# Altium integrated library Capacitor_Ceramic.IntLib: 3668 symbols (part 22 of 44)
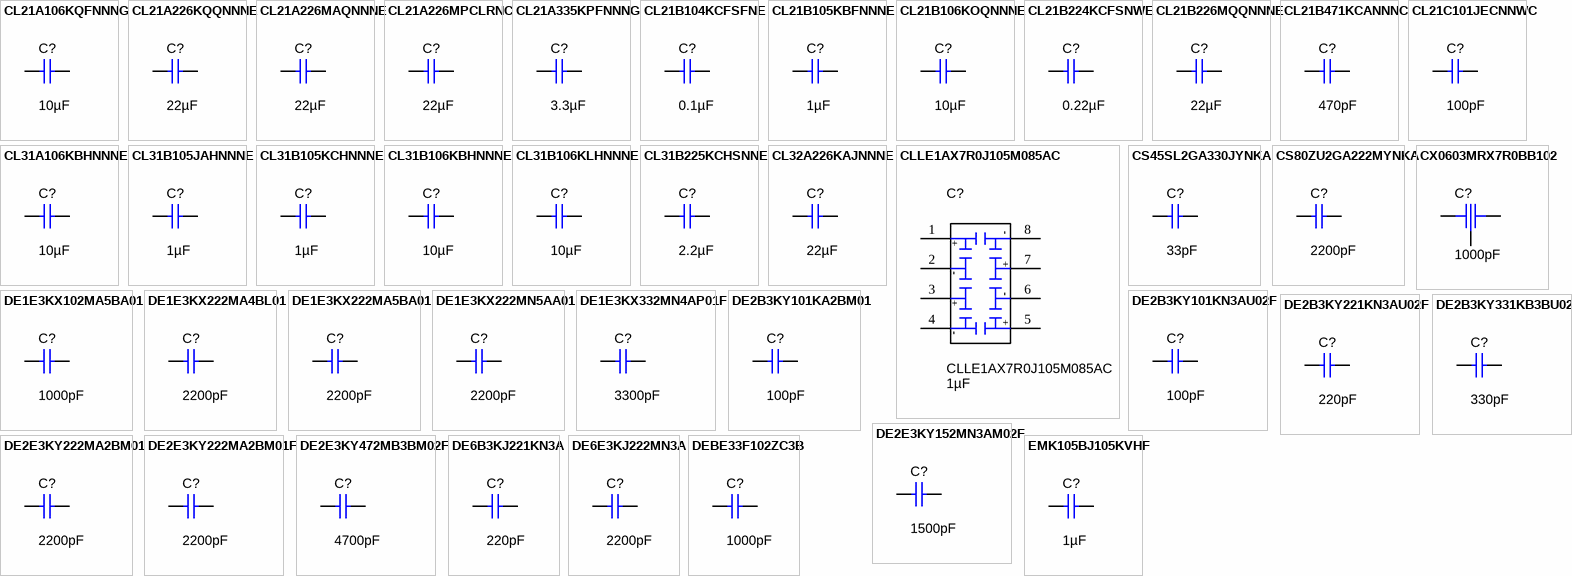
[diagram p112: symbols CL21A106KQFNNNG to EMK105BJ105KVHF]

## CL21C101JECNNWC
designator C?  ValueDisplayed: 100pF  (hidden comment: CL21C101JECNNWC)
CAP, CERM, 100 pF, 250 V,+/- 5%, C0G/NP0, 0805; Manufacturer: Samsung Electro-Mechanics; Polarized: N; CompType: Capacitor; Value: 100pF; U/M: EA; Cap_F: 0.0000000001; Tolerance_%: 5; VDC_V: 250; Value2: 250V; TaMin_C: -55; TaMax_C: 125; Cap_Case: 0805; SizeArea_mm2: 2.5; SizeAreaWB_mm2: 6.75; SizeX_mm: 2; SizeY_mm: 1.25; SizeZ_mm: 1.45; AEC Category: Q200
signal-integrity model Cap
simulation model Cap
footprint 0805_HV
footprint 0805_HV1
footprint 0805
footprint 0805M
footprint 0805L
pins: 1, 2

## CL31A106KBHNNNE
designator C?  ValueDisplayed: 10µF  (hidden comment: CL31A106KBHNNNE)
CAP, CERM, 10 µF, 50 V,+/- 10%, X5R, 1206; Manufacturer: Samsung Electro-Mechanics; Polarized: N; CompType: Capacitor; Value: 10uF; U/M: EA; Cap_F: 0.00001; Tolerance_%: 10; VDC_V: 50; Value2: 50V; TaMin_C: -55; TaMax_C: 85; Cap_Case: 1206; SizeArea_mm2: 5.12; SizeAreaWB_mm2: 10.92; SizeX_mm: 3.2; SizeY_mm: 1.6; SizeZ_mm: 1.9; AEC Category: Q200
signal-integrity model Cap
simulation model Cap
footprint 1206_190
footprint 1206_190M
footprint 1206_190L
pins: 1, 2

## CL31B105JAHNNNE
designator C?  ValueDisplayed: 1µF  (hidden comment: CL31B105JAHNNNE)
CAP, CERM, 1 µF, 25 V,+/- 5%, X7R, 1206; Manufacturer: Samsung Electro-Mechanics; Polarized: N; CompType: Capacitor; Value: 1uF; U/M: EA; Cap_F: 0.000001; Tolerance_%: 5; VDC_V: 25; Value2: 25V; TaMin_C: -55; TaMax_C: 125; Cap_Case: 1206; SizeArea_mm2: 5.12; SizeAreaWB_mm2: 10.92; SizeX_mm: 3.2; SizeY_mm: 1.6; SizeZ_mm: 1.9; AEC Category: Q200
signal-integrity model Cap
simulation model Cap
footprint 1206_190
footprint 1206_190M
footprint 1206_190L
pins: 1, 2

## CL31B105KCHNNNE
designator C?  ValueDisplayed: 1µF  (hidden comment: CL31B105KCHNNNE)
CAP, CERM, 1 µF, 100 V,+/- 10%, X7R, 1206; Manufacturer: Samsung Electro-Mechanics; Polarized: N; CompType: Capacitor; Value: 1uF; U/M: EA; Cap_F: 0.000001; Tolerance_%: 10; VDC_V: 100; Value2: 100V; TaMin_C: -55; TaMax_C: 125; Cap_Case: 1206; SizeArea_mm2: 5.12; SizeAreaWB_mm2: 10.92; SizeX_mm: 3.2; SizeY_mm: 1.6; SizeZ_mm: 1.8; AEC Category: Q200
signal-integrity model Cap
simulation model Cap
footprint 1206_180
footprint 1206_180M
footprint 1206_180L
pins: 1, 2

## CL31B106KBHNNNE
designator C?  ValueDisplayed: 10µF  (hidden comment: CL31B106KBHNNNE)
CAP, CERM, 10 µF, 50 V,+/- 10%, X7R, 1206; Manufacturer: Samsung Electro-Mechanics; Polarized: N; CompType: Capacitor; Value: 10uF; U/M: EA; Cap_F: 0.00001; Tolerance_%: 10; VDC_V: 50; Value2: 50V; TaMin_C: -55; TaMax_C: 125; Cap_Case: 1206; SizeArea_mm2: 5.12; SizeAreaWB_mm2: 10.92; SizeX_mm: 3.2; SizeY_mm: 1.6; SizeZ_mm: 1.8; AEC Category: Q200
signal-integrity model Cap
simulation model Cap
footprint 1206_180
footprint 1206_180M
footprint 1206_180L
pins: 1, 2

## CL31B106KLHNNNE
designator C?  ValueDisplayed: 10µF  (hidden comment: CL31B106KLHNNNE)
CAP, CERM, 10 µF, 35 V,+/- 10%, X7R, 1206; Manufacturer: Samsung Electro-Mechanics; Polarized: N; CompType: Capacitor; Value: 10uF; U/M: EA; Cap_F: 0.00001; Tolerance_%: 10; VDC_V: 35; Value2: 35V; TaMin_C: -55; TaMax_C: 125; Cap_Case: 1206; SizeArea_mm2: 5.12; SizeAreaWB_mm2: 10.92; SizeX_mm: 3.2; SizeY_mm: 1.6; SizeZ_mm: 1.9; AEC Category: Q200
signal-integrity model Cap
simulation model Cap
footprint 1206_190
footprint 1206_190M
footprint 1206_190L
pins: 1, 2

## CL31B225KCHSNNE
designator C?  ValueDisplayed: 2.2µF  (hidden comment: CL31B225KCHSNNE)
CAP, CERM, 2.2 µF, 100 V,+/- 10%, X7R, 1206; Manufacturer: Samsung Electro-Mechanics; Polarized: N; CompType: Capacitor; Value: 2.2uF; U/M: EA; Cap_F: 0.0000022; Tolerance_%: 10; VDC_V: 100; Value2: 100V; TaMin_C: -55; TaMax_C: 125; Cap_Case: 1206; SizeArea_mm2: 5.12; SizeAreaWB_mm2: 10.92; SizeX_mm: 3.2; SizeY_mm: 1.6; SizeZ_mm: 1.9; AEC Category: Q200; Green_Lifecycle: Active; Green_REACh: Passed
signal-integrity model Cap
simulation model Cap
footprint 1206_190
footprint 1206_190M
footprint 1206_190L
pins: 1, 2

## CL32A226KAJNNNE
designator C?  ValueDisplayed: 22µF  (hidden comment: CL32A226KAJNNNE)
CAP, CERM, 22 µF, 25 V,+/- 10%, X5R, 1210; Manufacturer: Samsung Electro-Mechanics; Polarized: N; CompType: Capacitor; Value: 22uF; U/M: EA; Cap_F: 0.000022; Tolerance_%: 10; VDC_V: 25; Value2: 25V; TaMin_C: -55; TaMax_C: 85; Cap_Case: 1210; SizeArea_mm2: 8; SizeAreaWB_mm2: 14.7; SizeX_mm: 3.2; SizeY_mm: 2.5; SizeZ_mm: 1.35; AEC Category: Q200
signal-integrity model Cap
simulation model Cap
footprint 1210
footprint 1210M
footprint 1210L
pins: 1, 2

## CLLE1AX7R0J105M085AC
designator C?  ValueDisplayed: 1µF
CAP, CERM, 1 µF, 6.3 V,+/- 20%, X7R, 0805; Manufacturer: TDK; SymbolCreator: a0411947; CompType: Capacitor; U/M: EA; Cap_F: 0.000001; Value: 1uF; Tolerance_%: 20; VDC_V: 6.3; Value2: 6.3V; TaMin_C: -55; TaMax_C: 125; Polarized: Y; Cap_Case: 0805; SizeArea_mm2: 2.5; SizeAreaWB_mm2: 6.75; SizeX_mm: 1.25; SizeY_mm: 2; SizeZ_mm: 0.95; AEC Category: Q200; AEC Qualified: N
footprint CLLE1A
pins: 1, 2, 3, 4, 5, 6, 7, 8

## CS45SL2GA330JYNKA
designator C?  ValueDisplayed: 33pF  (hidden comment: CS45SL2GA330JYNKA)
CAP, CERM, 33 pF, X1 440 VAC/Y2 300 VAC, +/- 5%, SL, D7xT5mm; Manufacturer: TDK; Polarized: N; CompType: Capacitor; Value: 33pF; U/M: EA; Cap_F: 0.000000000033; Tolerance_%: 5; TaMin_C: -25; TaMax_C: 125; Cap_Case: 7x5mm; SizeArea_mm2: 35; SizeAreaWB_mm2: 63; SizeX_mm: 7; SizeZ_mm: 11; AEC Category: Q200; AC_Safety: X1Y2; VAC_X: 440; VAC_Y: 300
signal-integrity model Cap
simulation model Cap
footprint TDK_700x500
pins: 1, 2

## CS80ZU2GA222MYNKA
designator C?  ValueDisplayed: 2200pF  (hidden comment: CS80ZU2GA222MYNKA)
CAP, CERM, 2200 pF, X1 440 VAC/Y2 300 VAC, +/- 20%, Z5U, D8xT5mm; Manufacturer: TDK; Polarized: N; CompType: Capacitor; Value: 2200pF; U/M: EA; Cap_F: 0.0000000022; Tolerance_%: 20; TaMin_C: 10; TaMax_C: 85; Cap_Case: 8x5x12mm; SizeArea_mm2: 40; SizeAreaWB_mm2: 70; SizeX_mm: 8; SizeY_mm: 5; SizeZ_mm: 12; AEC Category: Q200; AC_Safety: X1Y2; VAC_X: 440; VAC_Y: 300
signal-integrity model Cap
simulation model Cap
footprint CS_800x500x1200
pins: 1, 2

## CX0603MRX7R0BB102
designator C?  ValueDisplayed: 1000pF  (hidden comment: CX0603MRX7R0BB102)
CAP, CERM, 1000 pF, 100 V,+/- 20%, X7R, 0603; Manufacturer: Yageo America; SymbolCreator: a0411947; CompType: Capacitor; U/M: EA; Cap_F: 0.000000001; Value: 1000pF; Tolerance_%: 20; VDC_V: 100; Value2: 100V; TaMin_C: -55; TaMax_C: 125; Polarized: N; Cap_Case: 0603; SizeArea_mm2: 1.445514; SizeAreaWB_mm2: 4.960514; SizeX_mm: 1.626; SizeY_mm: 0.889; SizeZ_mm: 0.66; AEC Category: Q200
footprint X2Y_0603
pins: 1, 2, 3

## DE1E3KX102MA5BA01
designator C?  ValueDisplayed: 1000pF  (hidden comment: DE1E3KX102MA5BA01)
CAP, CERM, 1000 pF, X1 250 VAC/Y1 300 VAC, +/- 20%, E, Disc, 8x12mm; Manufacturer: MuRata; Polarized: N; CompType: Capacitor; Value: 1000pF; U/M: EA; Cap_F: 0.000000001; Tolerance_%: 20; TaMin_C: -25; TaMax_C: 85; Cap_Case: DE_800x1200x800; SizeArea_mm2: 64; SizeAreaWB_mm2: 100; SizeX_mm: 8; SizeZ_mm: 12; AEC Category: Q200; Green_Lifecycle: Not Set; Green_REACh: Incomplete; AC_Safety: X1Y1; VAC_X: 250; VAC_Y: 300
signal-integrity model Cap
simulation model Cap
footprint DE_800x1200x800
pins: 1, 2

## DE1E3KX222MA4BL01
designator C?  ValueDisplayed: 2200pF  (hidden comment: DE1E3KX222MA4BL01)
CAP, CERM, 2200 pF, X1 250 VAC/Y1 300 VAC, +/- 20%, E, Cap, 7x12x9 mm; Manufacturer: MuRata; Polarized: N; CompType: Capacitor; Value: 2200pF; U/M: EA; Cap_F: 0.0000000022; Tolerance_%: 20; TaMin_C: -25; TaMax_C: 85; Cap_Case: CAPRD1000W60D900H1200; SizeArea_mm2: 80.5; SizeAreaWB_mm2: 121.5; SizeX_mm: 11.5; SizeY_mm: 7; SizeZ_mm: 12.5; AEC Category: Q200; Green_Lifecycle: Not Set; Green_REACh: Incomplete; AC_Safety: X1Y1; VAC_X: 250; VAC_Y: 300
signal-integrity model Cap
simulation model Cap
footprint CAPRD1000W60D900H1200
pins: 1, 2

## DE1E3KX222MA5BA01
designator C?  ValueDisplayed: 2200pF  (hidden comment: DE1E3KX222MA5BA01)
CAP, CERM, 2200 pF, X1 250 VAC/Y1 300 VAC, +/- 20%, E, Disc 10x8mm; Manufacturer: MuRata; Polarized: N; CompType: Capacitor; Value: 2200pF; U/M: EA; Cap_F: 0.0000000022; Tolerance_%: 20; TaMin_C: -25; TaMax_C: 85; Cap_Case: CAPRD1000W60D1000H1400; SizeArea_mm2: 80; SizeAreaWB_mm2: 120; SizeX_mm: 10; SizeY_mm: 8; SizeZ_mm: 14; AEC Category: Q200; Green_Lifecycle: Not Set; Green_REACh: Incomplete; AC_Safety: X1Y1; VAC_X: 250; VAC_Y: 300
signal-integrity model Cap
simulation model Cap
footprint CAPRD1000W60D1000H1400
pins: 1, 2

## DE1E3KX222MN5AA01
designator C?  ValueDisplayed: 2200pF  (hidden comment: DE1E3KX222MN5AA01)
CAP, CERM, 2200 pF, X1 250 VAC/Y1 300 VAC, +/- 20%, E, 10.0x8.0x14.0mm; Manufacturer: MuRata; Polarized: N; CompType: Capacitor; Value: 2200pF; U/M: EA; Cap_F: 0.0000000022; Tolerance_%: 20; TaMin_C: -25; TaMax_C: 85; Cap_Case: 10x8x14mm; SizeArea_mm2: 80; SizeAreaWB_mm2: 120; SizeX_mm: 10; SizeY_mm: 8; SizeZ_mm: 14; AEC Category: Q200; AC_Safety: X1Y1; VAC_X: 250; VAC_Y: 300
signal-integrity model Cap
simulation model Cap
footprint KX_1000x800x1400
pins: 1, 2

## DE1E3KX332MN4AP01F
designator C?  ValueDisplayed: 3300pF  (hidden comment: DE1E3KX332MN4AP01F)
CAP, CERM, 3300 pF, X1 250 VAC/Y1 300 VAC, +/- 20%, E, D10xT7mm; Manufacturer: MuRata; Polarized: N; CompType: Capacitor; Value: 3300pF; U/M: EA; Cap_F: 0.0000000033; Tolerance_%: 20; TaMin_C: -40; TaMax_C: 125; Cap_Case: 10x7mm; SizeArea_mm2: 70; SizeAreaWB_mm2: 108; SizeX_mm: 10; SizeY_mm: 7; SizeZ_mm: 13; AEC Category: Q200; AC_Safety: X1Y1; VAC_X: 250; VAC_Y: 300
signal-integrity model Cap
simulation model Cap
footprint KX_1000x700
pins: 1, 2

## DE2B3KY101KA2BM01
designator C?  ValueDisplayed: 100pF  (hidden comment: DE2B3KY101KA2BM01)
CAP, CERM, 100 pF, X1 250 VAC/Y2 300 VAC, +/- 10%, B, Radial D7x5mm; Manufacturer: MuRata; Polarized: N; CompType: Capacitor; Value: 100pF; U/M: EA; Cap_F: 0.0000000001; Tolerance_%: 10; TaMin_C: -25; TaMax_C: 85; Cap_Case: CAPRD500W60D700H850; SizeArea_mm2: 35; SizeAreaWB_mm2: 63; SizeX_mm: 7; SizeY_mm: 5; AEC Category: Q200; AC_Safety: X1Y2; VAC_X: 250; VAC_Y: 300
signal-integrity model Cap
simulation model Cap
footprint CAPRD500W60D700H850
pins: 1, 2

## DE2B3KY101KN3AU02F
designator C?  ValueDisplayed: 100pF  (hidden comment: DE2B3KY101KN3AU02F)
CAP, CERM, 100 pF, X1 250 VAC/Y2 300 VAC, +/- 10%, B, TH, 2- Leads, Body 7x5mm, Pin Spacing 7.5mm; Manufacturer: MuRata; Polarized: N; CompType: Capacitor; Value: 100pF; U/M: EA; Cap_F: 0.0000000001; Tolerance_%: 10; TaMin_C: -25; TaMax_C: 85; Cap_Case: 7x5x10mm; SizeArea_mm2: 37.5; SizeAreaWB_mm2: 66.5; SizeX_mm: 7.5; SizeY_mm: 5; AEC Category: Q200; AC_Safety: X1Y2; VAC_X: 250; VAC_Y: 300
signal-integrity model Cap
simulation model Cap
footprint KY_700x500x1000
pins: 1, 2

## DE2B3KY221KN3AU02F
designator C?  ValueDisplayed: 220pF  (hidden comment: DE2B3KY221KN3AU02F)
CAP, CERM, 220 pF, X1 250 VAC/Y2 300 VAC, +/- 10%, B, TH, 2- Leads, Body 7x5mm, Pin Spacing 7.5mm; Manufacturer: MuRata; Polarized: N; CompType: Capacitor; Value: 220pF; U/M: EA; Cap_F: 0.00000000022; Tolerance_%: 10; TaMin_C: -25; TaMax_C: 85; Cap_Case: 7x5x10mm; SizeArea_mm2: 37.5; SizeAreaWB_mm2: 66.5; SizeX_mm: 7.5; SizeY_mm: 5; AEC Category: Q200; AC_Safety: X1Y2; VAC_X: 250; VAC_Y: 300
signal-integrity model Cap
simulation model Cap
footprint KY_700x500x1000
pins: 1, 2

## DE2B3KY331KB3BU02F
designator C?  ValueDisplayed: 330pF  (hidden comment: DE2B3KY331KB3BU02F)
CAP, CERM, 330 pF, X1 250 VAC/Y2 300 VAC, +/- 10%, B, TH, 2- Leads, Body 7x5mm, Pin Spacing 7.5mm; Manufacturer: MuRata; Polarized: N; CompType: Capacitor; Value: 330pF; U/M: EA; Cap_F: 0.00000000033; Tolerance_%: 10; TaMin_C: -25; TaMax_C: 85; Cap_Case: 7x5x10mm; SizeArea_mm2: 37.5; SizeAreaWB_mm2: 66.5; SizeX_mm: 7.5; SizeY_mm: 5; AEC Category: Q200; AC_Safety: X1Y2; VAC_X: 250; VAC_Y: 300
signal-integrity model Cap
simulation model Cap
footprint KY_700x500x1000
pins: 1, 2

## DE2E3KY152MN3AM02F
designator C?  ValueDisplayed: 1500pF  (hidden comment: DE2E3KY152MN3AM02F)
CAP, CERM, 1500 pF, X1 250 VAC/Y2 300 VAC, +/- 20%, E, TH, 2- Leads, Body 7x5mm, Pin Spacing 7.5mm; Manufacturer: MuRata; Polarized: N; CompType: Capacitor; Value: 1500pF; U/M: EA; Cap_F: 0.0000000015; Tolerance_%: 20; TaMin_C: -25; TaMax_C: 85; Cap_Case: 7x5x10mm; SizeArea_mm2: 37.5; SizeAreaWB_mm2: 66.5; SizeX_mm: 7.5; SizeY_mm: 5; SizeZ_mm: 10; AEC Category: Q200; AC_Safety: X1Y2; VAC_X: 250; VAC_Y: 300
signal-integrity model Cap
simulation model Cap
footprint KY_700x500x1000
pins: 1, 2

## DE2E3KY222MA2BM01
designator C?  ValueDisplayed: 2200pF  (hidden comment: DE2E3KY222MA2BM01)
CAP, CERM, 2200 pF, X1 250 VAC/Y2 300 VAC, +/- 20%, E, Radial D8x5mm; Manufacturer: MuRata; Polarized: N; CompType: Capacitor; Value: 2200pF; U/M: EA; Cap_F: 0.0000000022; Tolerance_%: 20; TaMin_C: -25; TaMax_C: 85; Cap_Case: CAPRD500W60D800H850; SizeArea_mm2: 40; SizeAreaWB_mm2: 70; SizeX_mm: 8; SizeY_mm: 5; SizeZ_mm: 11; AEC Category: Q200; Green_Lifecycle: Not Set; Green_REACh: Incomplete; AC_Safety: X1Y2; VAC_X: 250; VAC_Y: 300
signal-integrity model Cap
simulation model Cap
footprint CAPRD500W60D800H850
pins: 1, 2

## DE2E3KY222MA2BM01F
designator C?  ValueDisplayed: 2200pF  (hidden comment: DE2E3KY222MA2BM01F)
CAP, CERM, 2200 pF, X1 250 VAC/Y2 250 VAC, +/- 20%, E, 8x5mm; Manufacturer: MuRata; Polarized: N; CompType: Capacitor; Value: 2200pF; U/M: EA; Cap_F: 0.0000000022; Tolerance_%: 20; TaMin_C: -40; TaMax_C: 125; Cap_Case: 8x5x11mm; SizeArea_mm2: 40; SizeAreaWB_mm2: 70; SizeX_mm: 8; SizeY_mm: 5; SizeZ_mm: 11; AEC Category: Q200; AC_Safety: X1Y2; VAC_X: 250
signal-integrity model Cap
simulation model Cap
footprint KY_800x500x1100
pins: 1, 2

## DE2E3KY472MB3BM02F
designator C?  ValueDisplayed: 4700pF  (hidden comment: DE2E3KY472MB3BM02F)
CAP, CERM, 4700 pF, X1 250 VAC/Y2 300 VAC, +/- 20%, E, 10x5x13mm; Manufacturer: MuRata; Polarized: N; CompType: Capacitor; Value: 4700pF; U/M: EA; Cap_F: 0.0000000047; Tolerance_%: 20; TaMin_C: -40; TaMax_C: 125; SizeArea_mm2: 50; SizeAreaWB_mm2: 84; SizeX_mm: 10; SizeY_mm: 5; SizeZ_mm: 13; AEC Category: Q200; AC_Safety: X1Y2; VAC_X: 250; VAC_Y: 300
signal-integrity model Cap
simulation model Cap
footprint KY_1000x500x1300
pins: 1, 2

## DE6B3KJ221KN3A
designator C?  ValueDisplayed: 220pF  (hidden comment: DE6B3KJ221KN3A)
CAP, CERM, 220 pF, X1 440 VAC/Y2 300 VAC, +/- 10%, B, AEC-Q200 Grade 1, TH, 2- Leads, Body 8x7mm, Pin Spacing 7.5mm; Manufacturer: MuRata; Polarized: N; CompType: Capacitor; Value: 220pF; U/M: EA; Cap_F: 0.00000000022; Tolerance_%: 10; TaMin_C: -40; TaMax_C: 125; Cap_Case: 8x7x8mm; SizeArea_mm2: 56; SizeAreaWB_mm2: 90; SizeX_mm: 8; SizeY_mm: 7; SizeZ_mm: 11; AEC Category: Q200; AEC Qualified: Y; AEC Grade: 1; AC_Safety: X1Y2; VAC_X: 440; VAC_Y: 300
signal-integrity model Cap
simulation model Cap
footprint B_800x700x800
pins: 1, 2

## DE6E3KJ222MN3A
designator C?  ValueDisplayed: 2200pF  (hidden comment: DE6E3KJ222MN3A)
CAP, CERM, 2200 pF, X1 440 VAC/Y2 300 VAC, +/- 20%, E, AEC-Q200 Grade 1, TH, 2- Leads, Body 9x7mm, Pin Spacing 7.5mm; Manufacturer: MuRata; Polarized: N; CompType: Capacitor; Value: 2200pF; U/M: EA; Cap_F: 0.0000000022; Tolerance_%: 20; TaMin_C: -40; TaMax_C: 125; Cap_Case: 9x7x9mm; SizeArea_mm2: 63; SizeAreaWB_mm2: 99; SizeX_mm: 9; SizeY_mm: 7; SizeZ_mm: 12; AEC Category: Q200; AEC Qualified: Y; AEC Grade: 1; AC_Safety: X1Y2; VAC_X: 440; VAC_Y: 300
signal-integrity model Cap
simulation model Cap
footprint E_900x700x900
pins: 1, 2

## DEBE33F102ZC3B
designator C?  ValueDisplayed: 1000pF  (hidden comment: DEBE33F102ZC3B)
CAP, CERM, 1000 pF, 3150 V,+80/-20%, E, Radial Disc D7x6mm; Manufacturer: MuRata; Polarized: N; CompType: Capacitor; Value: 1000pF; U/M: EA; Cap_F: 0.000000001; Tolerance_%: 80; VDC_V: 3150; Value2: 3150V; TaMin_C: -25; TaMax_C: 85; Cap_Case: Disc, 7x6mm; SizeArea_mm2: 42; SizeAreaWB_mm2: 72; SizeX_mm: 7; SizeY_mm: 6; SizeZ_mm: 10; AEC Category: Q200
signal-integrity model Cap
simulation model Cap
footprint CAPRD750W60D700H1000
pins: 1, 2

## EMK105BJ105KVHF
designator C?  ValueDisplayed: 1µF  (hidden comment: EMK105BJ105KVHF)
CAP, CERM, 1 µF, 16 V,+/- 10%, X5R, 0402; Manufacturer: Taiyo Yuden; Polarized: N; CompType: Capacitor; Value: 1uF; U/M: EA; Cap_F: 0.000001; Tolerance_%: 10; VDC_V: 16; Value2: 16V; TaMin_C: -55; TaMax_C: 85; Cap_Case: 0402; SizeArea_mm2: 0.5; SizeAreaWB_mm2: 3; SizeX_mm: 1; SizeZ_mm: 0.6; AEC Category: Q200; Green_Lifecycle: Active; Green_REACh: Passed
signal-integrity model Cap
simulation model Cap
footprint 0402
footprint 0402M
footprint 0402L
footprint 0402S
pins: 1, 2

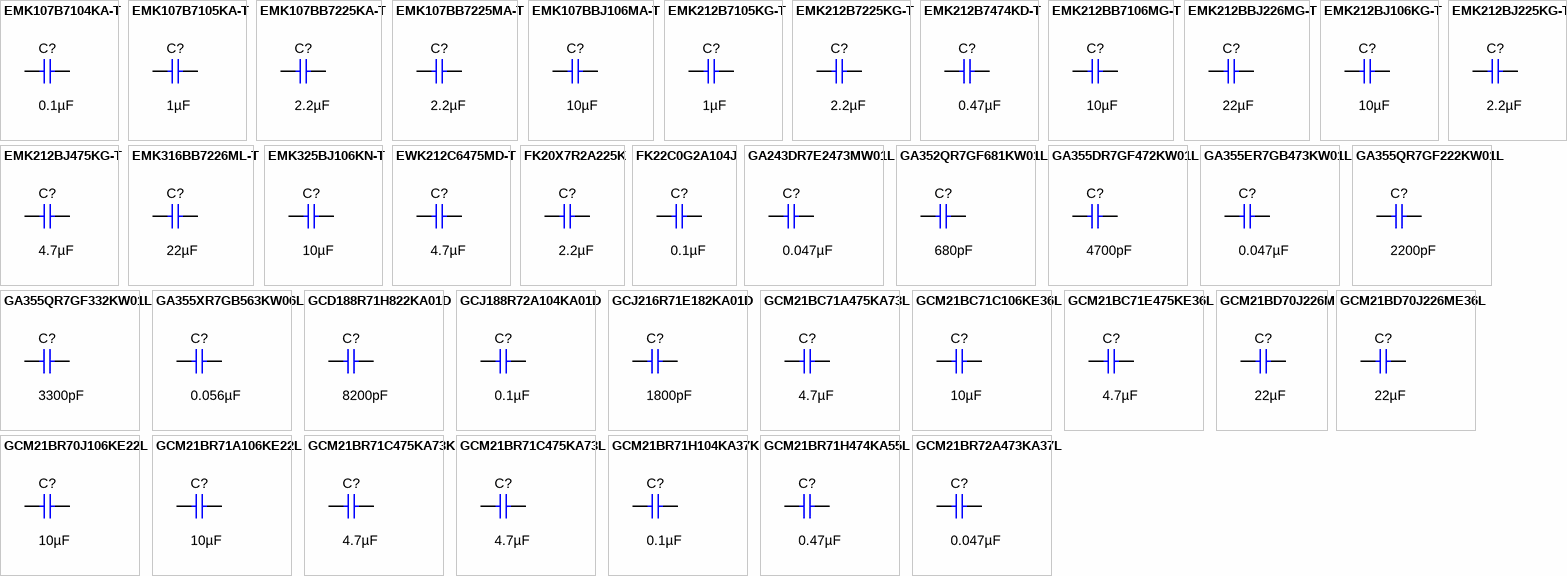
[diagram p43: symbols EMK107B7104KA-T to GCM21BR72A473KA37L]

## EMK107B7104KA-T
designator C?  ValueDisplayed: 0.1µF  (hidden comment: EMK107B7104KA-T)
CAP, CERM, 0.1 µF, 16 V,+/- 10%, X7R, 0603; Manufacturer: Taiyo Yuden; Polarized: N; CompType: Capacitor; Value: 0.1uF; U/M: EA; Cap_F: 0.0000001; Tolerance_%: 10; VDC_V: 16; Value2: 16V; TaMin_C: -55; TaMax_C: 125; Cap_Case: 0603; SizeArea_mm2: 1.28; SizeAreaWB_mm2: 4.68; SizeX_mm: 1.6; SizeY_mm: 0.8; SizeZ_mm: 1; AEC Category: Q200; Green_Lifecycle: Not Set; Green_REACh: Incomplete
signal-integrity model Cap
simulation model Cap
footprint 0603
footprint 0603M
footprint 0603L
footprint 0603_HV
footprint 0603S
pins: 1, 2

## EMK107B7105KA-T
designator C?  ValueDisplayed: 1µF  (hidden comment: EMK107B7105KA-T)
CAP, CERM, 1 µF, 16 V,+/- 10%, X7R, 0603; Manufacturer: Taiyo Yuden; Polarized: N; CompType: Capacitor; Value: 1uF; U/M: EA; Cap_F: 0.000001; Tolerance_%: 10; VDC_V: 16; Value2: 16V; TaMin_C: -55; TaMax_C: 85; Cap_Case: 0603; SizeArea_mm2: 1.28; SizeAreaWB_mm2: 4.68; SizeX_mm: 1.6; SizeY_mm: 0.8; SizeZ_mm: 1; AEC Category: Q200; Green_Lifecycle: Active; Green_REACh: Passed
signal-integrity model Cap
simulation model Cap
footprint 0603
footprint 0603M
footprint 0603L
footprint 0603_HV
footprint 0603S
pins: 1, 2

## EMK107BB7225KA-T
designator C?  ValueDisplayed: 2.2µF  (hidden comment: EMK107BB7225KA-T)
CAP, CERM, 2.2 µF, 16 V,+/- 10%, X7R, 0603; Manufacturer: Taiyo Yuden; Polarized: N; CompType: Capacitor; Value: 2.2uF; U/M: EA; Cap_F: 0.0000022; Tolerance_%: 10; VDC_V: 16; Value2: 16V; TaMin_C: -55; TaMax_C: 125; Cap_Case: 0603; SizeArea_mm2: 1.28; SizeAreaWB_mm2: 4.68; SizeX_mm: 1.6; SizeY_mm: 0.8; SizeZ_mm: 1; AEC Category: Q200; Green_Lifecycle: Active; Green_REACh: Passed
signal-integrity model Cap
simulation model Cap
footprint 0603
footprint 0603M
footprint 0603L
footprint 0603_HV
footprint 0603S
pins: 1, 2

## EMK107BB7225MA-T
designator C?  ValueDisplayed: 2.2µF  (hidden comment: EMK107BB7225MA-T)
CAP, CERM, 2.2 µF, 16 V,+/- 10%, X7R, 0603; Manufacturer: Taiyo Yuden; Polarized: N; CompType: Capacitor; Value: 2.2uF; U/M: EA; Cap_F: 0.0000022; Tolerance_%: 10; VDC_V: 16; Value2: 16V; TaMin_C: -55; TaMax_C: 125; Cap_Case: 0603; SizeArea_mm2: 1.28; SizeAreaWB_mm2: 4.68; SizeX_mm: 1.6; SizeY_mm: 0.8; SizeZ_mm: 1; AEC Category: Q200
signal-integrity model Cap
simulation model Cap
footprint 0603
footprint 0603M
footprint 0603L
footprint 0603_HV
footprint 0603S
pins: 1, 2

## EMK107BBJ106MA-T
designator C?  ValueDisplayed: 10µF  (hidden comment: EMK107BBJ106MA-T)
CAP, CERM, 10 µF, 16 V,+/- 20%, X5R, 0603; Manufacturer: Taiyo Yuden; Polarized: N; CompType: Capacitor; Value: 10uF; U/M: EA; Cap_F: 0.00001; Tolerance_%: 20; VDC_V: 16; Value2: 16V; TaMin_C: -55; TaMax_C: 85; Cap_Case: 0603; SizeArea_mm2: 1.28; SizeAreaWB_mm2: 4.68; SizeX_mm: 1.6; SizeY_mm: 0.8; SizeZ_mm: 1; AEC Category: Q200; Green_Lifecycle: Active; Green_REACh: Passed
signal-integrity model Cap
simulation model Cap
footprint 0603
footprint 0603M
footprint 0603L
footprint 0603_HV
footprint 0603S
pins: 1, 2

## EMK212B7105KG-T
designator C?  ValueDisplayed: 1µF  (hidden comment: EMK212B7105KG-T)
CAP, CERM, 1 µF, 16 V,+/- 10%, X7R, 0805; Manufacturer: Taiyo Yuden; Polarized: N; CompType: Capacitor; Value: 1uF; U/M: EA; Cap_F: 0.000001; Tolerance_%: 10; VDC_V: 16; Value2: 16V; TaMin_C: -55; TaMax_C: 125; Cap_Case: 0805; SizeArea_mm2: 2.5; SizeAreaWB_mm2: 6.75; SizeX_mm: 2; SizeY_mm: 1.25; SizeZ_mm: 1.45; AEC Category: Q200; Green_Lifecycle: Active; Green_REACh: Passed
signal-integrity model Cap
simulation model Cap
footprint 0805_HV
footprint 0805_HV1
footprint 0805
footprint 0805M
footprint 0805L
pins: 1, 2

## EMK212B7225KG-T
designator C?  ValueDisplayed: 2.2µF  (hidden comment: EMK212B7225KG-T)
CAP, CERM, 2.2 µF, 16 V,+/- 10%, X7R, 0805; Manufacturer: Taiyo Yuden; Polarized: N; CompType: Capacitor; Value: 2.2uF; U/M: EA; Cap_F: 0.0000022; Tolerance_%: 10; VDC_V: 16; Value2: 16V; TaMin_C: -55; TaMax_C: 125; Cap_Case: 0805; SizeArea_mm2: 2.5; SizeAreaWB_mm2: 6.75; SizeX_mm: 2; SizeY_mm: 1.25; SizeZ_mm: 1.45; AEC Category: Q200; Green_Lifecycle: Active; Green_REACh: Passed
signal-integrity model Cap
simulation model Cap
footprint 0805_HV
footprint 0805_HV1
footprint 0805
footprint 0805M
footprint 0805L
pins: 1, 2

## EMK212B7474KD-T
designator C?  ValueDisplayed: 0.47µF  (hidden comment: EMK212B7474KD-T)
CAP, CERM, 0.47 µF, 16 V,+/- 10%, X7R, 0805; Manufacturer: Taiyo Yuden; Polarized: N; CompType: Capacitor; Value: 0.47uF; U/M: EA; Cap_F: 0.00000047; Tolerance_%: 10; VDC_V: 16; Value2: 16V; TaMin_C: -55; TaMax_C: 125; Cap_Case: 0805; SizeArea_mm2: 2.5; SizeAreaWB_mm2: 6.75; SizeX_mm: 2; SizeY_mm: 1.25; SizeZ_mm: 1.45; AEC Category: Q200; Green_Lifecycle: Active; Green_REACh: Passed
signal-integrity model Cap
simulation model Cap
footprint 0805_HV
footprint 0805_HV1
footprint 0805
footprint 0805M
footprint 0805L
pins: 1, 2

## EMK212BB7106MG-T
designator C?  ValueDisplayed: 10µF  (hidden comment: EMK212BB7106MG-T)
CAP, CERM, 10 µF, 16 V,+/- 20%, X7R, 0805; Manufacturer: Taiyo Yuden; Polarized: N; CompType: Capacitor; Value: 10uF; U/M: EA; Cap_F: 0.00001; Tolerance_%: 20; VDC_V: 16; Value2: 16V; TaMin_C: -55; TaMax_C: 125; Cap_Case: 0805; SizeArea_mm2: 2.5; SizeAreaWB_mm2: 6.75; SizeX_mm: 2; SizeY_mm: 1.25; SizeZ_mm: 1.45; AEC Category: Q200; Green_Lifecycle: Active; Green_REACh: Passed
signal-integrity model Cap
simulation model Cap
footprint 0805_HV
footprint 0805_HV1
footprint 0805
footprint 0805M
footprint 0805L
pins: 1, 2

## EMK212BBJ226MG-T
designator C?  ValueDisplayed: 22µF  (hidden comment: EMK212BBJ226MG-T)
CAP, CERM, 22 µF, 16 V,+/- 20%, X5R, 0805; Manufacturer: Taiyo Yuden; Polarized: N; CompType: Capacitor; Value: 22uF; U/M: EA; Cap_F: 0.000022; Tolerance_%: 20; VDC_V: 16; Value2: 16V; TaMin_C: -55; TaMax_C: 85; Cap_Case: 0805; SizeArea_mm2: 2.5; SizeAreaWB_mm2: 6.75; SizeX_mm: 2; SizeY_mm: 1.25; SizeZ_mm: 1.45; AEC Category: Q200; Green_Lifecycle: Active; Green_REACh: Passed
signal-integrity model Cap
simulation model Cap
footprint 0805_HV
footprint 0805_HV1
footprint 0805
footprint 0805M
footprint 0805L
pins: 1, 2

## EMK212BJ106KG-T
designator C?  ValueDisplayed: 10µF  (hidden comment: EMK212BJ106KG-T)
CAP, CERM, 10 µF, 16 V,+/- 10%, X5R, 0805; Manufacturer: Taiyo Yuden; Polarized: N; CompType: Capacitor; Value: 10uF; U/M: EA; Cap_F: 0.00001; Tolerance_%: 10; VDC_V: 16; Value2: 16V; TaMin_C: -55; TaMax_C: 85; Cap_Case: 0805; SizeArea_mm2: 2.5; SizeAreaWB_mm2: 6.75; SizeX_mm: 2; SizeY_mm: 1.25; SizeZ_mm: 1.45; AEC Category: Q200; Green_Lifecycle: Not Set; Green_REACh: Incomplete
signal-integrity model Cap
simulation model Cap
footprint 0805_HV
footprint 0805_HV1
footprint 0805
footprint 0805M
footprint 0805L
pins: 1, 2

## EMK212BJ225KG-T
designator C?  ValueDisplayed: 2.2µF  (hidden comment: EMK212BJ225KG-T)
CAP, CERM, 2.2 µF, 16 V,+/- 10%, X5R, 0805; Manufacturer: Taiyo Yuden; Polarized: N; CompType: Capacitor; Value: 2.2uF; U/M: EA; Cap_F: 0.0000022; Tolerance_%: 10; VDC_V: 16; Value2: 16V; TaMin_C: -55; TaMax_C: 85; Cap_Case: 0805; SizeArea_mm2: 2.5; SizeAreaWB_mm2: 6.75; SizeX_mm: 2; SizeY_mm: 1.25; SizeZ_mm: 1.45; AEC Category: Q200; Green_Lifecycle: Active; Green_REACh: Passed
signal-integrity model Cap
simulation model Cap
footprint 0805_HV
footprint 0805_HV1
footprint 0805
footprint 0805M
footprint 0805L
pins: 1, 2

## EMK212BJ475KG-T
designator C?  ValueDisplayed: 4.7µF  (hidden comment: EMK212BJ475KG-T)
CAP, CERM, 4.7 µF, 16 V,+/- 10%, X5R, 0805; Manufacturer: Taiyo Yuden; Polarized: N; CompType: Capacitor; Value: 4.7uF; U/M: EA; Cap_F: 0.0000047; Tolerance_%: 10; VDC_V: 16; Value2: 16V; TaMin_C: -55; TaMax_C: 85; Cap_Case: 0805; SizeArea_mm2: 2.5; SizeAreaWB_mm2: 6.75; SizeX_mm: 2; SizeY_mm: 1.25; SizeZ_mm: 1.45; AEC Category: Q200
signal-integrity model Cap
simulation model Cap
footprint 0805_HV
footprint 0805_HV1
footprint 0805
footprint 0805M
footprint 0805L
pins: 1, 2

## EMK316BB7226ML-T
designator C?  ValueDisplayed: 22µF  (hidden comment: EMK316BB7226ML-T)
CAP, CERM, 22 µF, 16 V,+/- 20%, X7R, 1206; Manufacturer: Taiyo Yuden; Polarized: N; CompType: Capacitor; Value: 22uF; U/M: EA; Cap_F: 0.000022; Tolerance_%: 20; VDC_V: 16; Value2: 16V; TaMin_C: -55; TaMax_C: 125; Cap_Case: 1206; SizeArea_mm2: 5.12; SizeAreaWB_mm2: 10.92; SizeX_mm: 3.2; SizeY_mm: 1.6; SizeZ_mm: 1.9; AEC Category: Q200
signal-integrity model Cap
simulation model Cap
footprint 1206_190
footprint 1206_190M
footprint 1206_190L
pins: 1, 2

## EMK325BJ106KN-T
designator C?  ValueDisplayed: 10µF  (hidden comment: EMK325BJ106KN-T)
CAP, CERM, 10 µF, 16 V,+/- 20%, X5R, 1210; Manufacturer: Taiyo Yuden; Polarized: N; CompType: Capacitor; Value: 10uF; U/M: EA; Cap_F: 0.00001; Tolerance_%: 20; ESR_ohm: 0.008; Value1: 0.008 ohm; VDC_V: 16; Value2: 16V; TaMin_C: -55; TaMax_C: 125; Cap_Case: 1210; SizeArea_mm2: 8; SizeAreaWB_mm2: 14.7; SizeX_mm: 3.2; SizeY_mm: 2.5; SizeZ_mm: 1.35; AEC Category: Q200; Green_Lifecycle: Active; Green_REACh: Passed
signal-integrity model Cap
simulation model Cap
footprint 1210
footprint 1210M
footprint 1210L
pins: 1, 2

## EWK212C6475MD-T
designator C?  ValueDisplayed: 4.7µF  (hidden comment: EWK212C6475MD-T)
CAP, CERM, 4.7 µF, 16 V,+/- 20%, X6S, 0508; Manufacturer: Taiyo Yuden; Polarized: N; CompType: Capacitor; Value: 4.7uF; U/M: EA; Cap_F: 0.0000047; Tolerance_%: 20; VDC_V: 16; Value2: 16V; TaMin_C: -55; TaMax_C: 105; Cap_Case: 0508; SizeArea_mm2: 2.5; SizeAreaWB_mm2: 6.75; SizeX_mm: 1.25; SizeY_mm: 2; SizeZ_mm: 1; AEC Category: Q200
signal-integrity model Cap
simulation model Cap
footprint 0508
pins: 1, 2

## FK20X7R2A225K
designator C?  ValueDisplayed: 2.2µF  (hidden comment: FK20X7R2A225K)
CAP, CERM, 2.2 µF, 100 V,+/- 10%, X7R, 5.50x7.00x4.00mm; Manufacturer: TDK; Polarized: N; CompType: Capacitor; Value: 2.2uF; U/M: EA; Cap_F: 0.0000022; Tolerance_%: 10; VDC_V: 100; Value2: 100V; TaMin_C: -55; TaMax_C: 125; Cap_Case: FK_550x700x400; SizeArea_mm2: 22; SizeAreaWB_mm2: 45; SizeX_mm: 5.5; SizeY_mm: 4; SizeZ_mm: 7; AEC Category: Q200
signal-integrity model Cap
simulation model Cap
footprint FK_550x700x400
pins: 1, 2

## FK22C0G2A104J
designator C?  ValueDisplayed: 0.1µF  (hidden comment: FK22C0G2A104J)
CAP, CERM, 0.1 µF, 100 V,+/- 5%, C0G/NP0, 7.5x4mm; Manufacturer: TDK; Polarized: N; CompType: Capacitor; Value: 0.1uF; U/M: EA; Cap_F: 0.0000001; Tolerance_%: 5; VDC_V: 100; Value2: 100V; TaMin_C: -55; TaMax_C: 125; Cap_Case: 7.5x4x8mm; SizeArea_mm2: 30; SizeAreaWB_mm2: 57; SizeX_mm: 7.5; SizeY_mm: 4; SizeZ_mm: 8; AEC Category: Q200
signal-integrity model Cap
simulation model Cap
footprint FK22
pins: 1, 2

## GA243DR7E2473MW01L
designator C?  ValueDisplayed: 0.047µF  (hidden comment: GA243DR7E2473MW01L)
CAP, CERM, 0.047 µF, 250 V,+/- 20%, X7R, 1812; Manufacturer: MuRata; Polarized: N; CompType: Capacitor; Value: 0.047uF; U/M: EA; Cap_F: 0.000000047; Tolerance_%: 20; VDC_V: 250; Value2: 250V; TaMin_C: -55; TaMax_C: 125; Cap_Case: 1812; SizeArea_mm2: 14.4; SizeAreaWB_mm2: 23.1; SizeX_mm: 4.5; SizeY_mm: 3.2; SizeZ_mm: 2.2; AEC Category: Q200
signal-integrity model Cap
simulation model Cap
footprint 1812_220
footprint 1812_220M
footprint 1812_220L
pins: 1, 2

## GA352QR7GF681KW01L
designator C?  ValueDisplayed: 680pF  (hidden comment: GA352QR7GF681KW01L)
CAP, CERM, 680 pF, X1 250 VAC/Y2 250 VAC, +/- 10%, X7R, 2211; Manufacturer: MuRata; Polarized: N; CompType: Capacitor; Value: 680pF; U/M: EA; Cap_F: 0.00000000068; Tolerance_%: 10; VDC_V: 0; Value2: 0V; TaMin_C: -55; TaMax_C: 125; Cap_Case: 2211; SizeArea_mm2: 15.96; SizeAreaWB_mm2: 36.96; SizeX_mm: 5.7; SizeY_mm: 2.8; SizeZ_mm: 1.5; AEC Category: Q200; AC_Safety: X1Y2; VAC_X: 250
signal-integrity model Cap
simulation model Cap
footprint 2211
pins: 1, 2

## GA355DR7GF472KW01L
designator C?  ValueDisplayed: 4700pF  (hidden comment: GA355DR7GF472KW01L)
CAP, CERM, 4700 pF, 250 V,+/- 10%, X7R, 2220; Manufacturer: MuRata; Polarized: N; CompType: Capacitor; Value: 4700pF; U/M: EA; Cap_F: 0.0000000047; Tolerance_%: 10; VDC_V: 250; Value2: 250V; TaMin_C: -55; TaMax_C: 125; Cap_Case: 2220; SizeArea_mm2: 28.5; SizeAreaWB_mm2: 53.9; SizeX_mm: 5.7; SizeY_mm: 5; SizeZ_mm: 2.8; AEC Category: Q200; Green_Lifecycle: Not Set; Green_REACh: Incomplete
signal-integrity model Cap
simulation model Cap
footprint 2220_280
footprint 2220_280M
footprint 2220_280L
pins: 1, 2

## GA355ER7GB473KW01L
designator C?  ValueDisplayed: 0.047µF  (hidden comment: GA355ER7GB473KW01L)
CAP, CERM, 0.047 µF, 250 V,+/- 10%, X7R, 2220; Manufacturer: MuRata; Polarized: N; CompType: Capacitor; Value: 0.047uF; U/M: EA; Cap_F: 0.000000047; Tolerance_%: 10; VDC_V: 250; Value2: 250V; TaMin_C: -55; TaMax_C: 125; Cap_Case: 2220; SizeArea_mm2: 28.5; SizeAreaWB_mm2: 53.9; SizeX_mm: 5.7; SizeY_mm: 5; SizeZ_mm: 2.8; AEC Category: Q200
signal-integrity model Cap
simulation model Cap
footprint 2220_280
footprint 2220_280M
footprint 2220_280L
pins: 1, 2

## GA355QR7GF222KW01L
designator C?  ValueDisplayed: 2200pF  (hidden comment: GA355QR7GF222KW01L)
CAP, CERM, 2200 pF, 250 V,+/- 10%, X7R, 2220; Manufacturer: MuRata; Polarized: N; CompType: Capacitor; Value: 2200pF; U/M: EA; Cap_F: 0.0000000022; Tolerance_%: 10; VDC_V: 250; Value2: 250V; TaMin_C: -55; TaMax_C: 125; Cap_Case: 2220; SizeArea_mm2: 28.5; SizeAreaWB_mm2: 53.9; SizeX_mm: 5.7; SizeY_mm: 5; SizeZ_mm: 2.8; AEC Category: Q200; Green_Lifecycle: Not Set; Green_REACh: Incomplete
signal-integrity model Cap
simulation model Cap
footprint 2220_280
footprint 2220_280M
footprint 2220_280L
pins: 1, 2

## GA355QR7GF332KW01L
designator C?  ValueDisplayed: 3300pF  (hidden comment: GA355QR7GF332KW01L)
CAP, CERM, 3300 pF, 250 V,+/- 10%, X7R, 2220; Manufacturer: MuRata; Polarized: N; CompType: Capacitor; Value: 3300pF; U/M: EA; Cap_F: 0.0000000033; Tolerance_%: 10; VDC_V: 250; Value2: 250V; TaMin_C: -55; TaMax_C: 125; Cap_Case: 2220; SizeArea_mm2: 28.5; SizeAreaWB_mm2: 53.9; SizeX_mm: 5.7; SizeY_mm: 5; SizeZ_mm: 2.8; AEC Category: Q200
signal-integrity model Cap
simulation model Cap
footprint 2220_280
footprint 2220_280M
footprint 2220_280L
pins: 1, 2

## GA355XR7GB563KW06L
designator C?  ValueDisplayed: 0.056µF  (hidden comment: GA355XR7GB563KW06L)
CAP, CERM, 0.056 µF, 250 V,+/- 10%, X7R, 2220; Manufacturer: MuRata; Polarized: N; CompType: Capacitor; Value: 0.056uF; U/M: EA; Cap_F: 0.000000056; Tolerance_%: 10; VDC_V: 250; Value2: 250V; TaMin_C: -55; TaMax_C: 125; Cap_Case: 2220; SizeArea_mm2: 28.5; SizeAreaWB_mm2: 53.9; SizeX_mm: 5.7; SizeY_mm: 5; SizeZ_mm: 3.3; AEC Category: Q200
signal-integrity model Cap
simulation model Cap
footprint 2220_330_N
footprint 2220_330_M
footprint 2220_330_L
pins: 1, 2

## GCD188R71H822KA01D
designator C?  ValueDisplayed: 8200pF  (hidden comment: GCD188R71H822KA01D)
CAP, CERM, 8200 pF, 50 V,+/- 10%, X7R, AEC-Q200 Grade 1, 0603; Manufacturer: MuRata; Polarized: N; CompType: Capacitor; Value: 8200pF; U/M: EA; Cap_F: 0.0000000082; Tolerance_%: 10; VDC_V: 50; Value2: 50V; TaMin_C: -55; TaMax_C: 125; Cap_Case: 0603; SizeArea_mm2: 1.28; SizeAreaWB_mm2: 4.68; SizeX_mm: 1.6; SizeY_mm: 0.8; SizeZ_mm: 1; AEC Category: Q200; AEC Qualified: Y
signal-integrity model Cap
simulation model Cap
footprint 0603
footprint 0603M
footprint 0603L
footprint 0603_HV
footprint 0603S
pins: 1, 2

## GCJ188R72A104KA01D
designator C?  ValueDisplayed: 0.1µF  (hidden comment: GCJ188R72A104KA01D)
CAP, CERM, 0.1 µF, 100 V,+/- 10%, X7R, AEC-Q200 Grade 1, 0603; Manufacturer: MuRata; Polarized: N; CompType: Capacitor; Value: 0.1uF; U/M: EA; Cap_F: 0.0000001; Tolerance_%: 10; VDC_V: 100; Value2: 100V; TaMin_C: -55; TaMax_C: 125; Cap_Case: 0603; SizeArea_mm2: 1.28; SizeAreaWB_mm2: 4.68; SizeX_mm: 1.6; SizeY_mm: 0.8; SizeZ_mm: 1; AEC Category: Q200; AEC Qualified: Y
signal-integrity model Cap
simulation model Cap
footprint 0603
footprint 0603M
footprint 0603L
footprint 0603_HV
footprint 0603S
pins: 1, 2

## GCJ216R71E182KA01D
designator C?  ValueDisplayed: 1800pF  (hidden comment: GCJ216R71E182KA01D)
CAP, CERM, 1800 pF, 25 V,+/- 10%, X7R, AEC-Q200 Grade 1, 0603; Manufacturer: MuRata; Polarized: N; CompType: Capacitor; Value: 1800pF; U/M: EA; Cap_F: 0.0000000018; Tolerance_%: 10; VDC_V: 25; Value2: 25V; TaMin_C: -55; TaMax_C: 125; Cap_Case: 0603; SizeArea_mm2: 1.28; SizeAreaWB_mm2: 4.68; SizeX_mm: 1.6; SizeY_mm: 0.8; SizeZ_mm: 1; AEC Category: Q200; AEC Qualified: Y
signal-integrity model Cap
simulation model Cap
footprint 0603
footprint 0603M
footprint 0603L
footprint 0603_HV
footprint 0603S
pins: 1, 2

## GCM21BC71A475KA73L
designator C?  ValueDisplayed: 4.7µF  (hidden comment: GCM21BC71A475KA73L)
CAP, CERM, 4.7 µF, 10 V,+/- 10%, X7S, AEC-Q200 Grade 1, 0805; Manufacturer: MuRata; Polarized: N; CompType: Capacitor; Value: 4.7uF; U/M: EA; Cap_F: 0.0000047; Tolerance_%: 10; Value2: 10V; TaMin_C: -55; TaMax_C: 125; Cap_Case: 0805; SizeArea_mm2: 2.5; SizeAreaWB_mm2: 6.75; SizeX_mm: 2; SizeY_mm: 1.25; SizeZ_mm: 1.45; AEC Category: Q200; AEC Qualified: Y; AEC Grade: 1
signal-integrity model Cap
simulation model Cap
footprint 0805_HV
footprint 0805_HV1
footprint 0805
footprint 0805M
footprint 0805L
pins: 1, 2

## GCM21BC71C106KE36L
designator C?  ValueDisplayed: 10µF  (hidden comment: GCM21BC71C106KE36L)
CAP, CERM, 10 µF, 16 V,+/- 10%, X7S, AEC-Q200 Grade 1, 0805; Manufacturer: MuRata; Polarized: N; CompType: Capacitor; Value: 10uF; U/M: EA; Cap_F: 0.00001; Tolerance_%: 10; VDC_V: 16; Value2: 16V; TaMin_C: -55; TaMax_C: 125; Cap_Case: 0805; SizeArea_mm2: 2.5; SizeAreaWB_mm2: 6.75; SizeX_mm: 2; SizeY_mm: 1.25; SizeZ_mm: 1.45; AEC Category: Q200; AEC Qualified: Y; AEC Grade: 1
signal-integrity model Cap
simulation model Cap
footprint 0805_HV
footprint 0805_HV1
footprint 0805
footprint 0805M
footprint 0805L
pins: 1, 2

## GCM21BC71E475KE36L
designator C?  ValueDisplayed: 4.7µF  (hidden comment: GCM21BC71E475KE36L)
CAP, CERM, 4.7 µF, 25 V,+/- 10%, X7S, AEC-Q200 Grade 1, 0805; Manufacturer: MuRata; Polarized: N; CompType: Capacitor; Value: 4.7uF; U/M: EA; Cap_F: 0.0000047; Tolerance_%: 10; VDC_V: 25; Value2: 25V; TaMin_C: -55; TaMax_C: 125; Cap_Case: 0805; SizeArea_mm2: 2.5; SizeAreaWB_mm2: 6.75; SizeX_mm: 2; SizeY_mm: 1.25; SizeZ_mm: 1.45; AEC Category: Q200; AEC Qualified: Y; AEC Grade: 1
signal-integrity model Cap
simulation model Cap
footprint 0805_HV
footprint 0805_HV1
footprint 0805
footprint 0805M
footprint 0805L
pins: 1, 2

## GCM21BD70J226M
designator C?  ValueDisplayed: 22µF  (hidden comment: GCM21BD70J226M)
CAP, CERM, 22 µF, 6.3 V,+/- 20%, X7T, 0805; Manufacturer: MuRata; Polarized: N; CompType: Capacitor; Value: 22uF; U/M: EA; Cap_F: 0.000022; Tolerance_%: 20; VDC_V: 6.3; Value2: 6.3V; TaMin_C: -55; TaMax_C: 125; Cap_Case: 0805; SizeArea_mm2: 2.5; SizeAreaWB_mm2: 6.75; SizeX_mm: 2; SizeY_mm: 1.25; SizeZ_mm: 1.45; AEC Category: Q200
signal-integrity model Cap
simulation model Cap
footprint 0805_HV
footprint 0805_HV1
footprint 0805
footprint 0805M
footprint 0805L
pins: 1, 2

## GCM21BD70J226ME36L
designator C?  ValueDisplayed: 22µF  (hidden comment: GCM21BD70J226ME36L)
CAP, CERM, 22 µF, 6.3 V,+/- 20%, X7T, AEC-Q200 Grade 1, 0805; Manufacturer: MuRata; Polarized: N; CompType: Capacitor; Value: 22uF; U/M: EA; Cap_F: 0.000022; Tolerance_%: 20; VDC_V: 6.3; Value2: 6.3V; TaMin_C: -55; TaMax_C: 125; Cap_Case: 0805; SizeArea_mm2: 2.5; SizeAreaWB_mm2: 6.75; SizeX_mm: 2; SizeY_mm: 1.25; SizeZ_mm: 1.45; AEC Category: Q200; AEC Qualified: Y; AEC Grade: 1
signal-integrity model Cap
simulation model Cap
footprint 0805_HV
footprint 0805_HV1
footprint 0805
footprint 0805M
footprint 0805L
pins: 1, 2

## GCM21BR70J106KE22L
designator C?  ValueDisplayed: 10µF  (hidden comment: GCM21BR70J106KE22L)
CAP, CERM, 10 µF, 6.3 V,+/- 10%, X7R, AEC-Q200 Grade 1, 0805; Manufacturer: MuRata; Polarized: N; CompType: Capacitor; Value: 10uF; U/M: EA; Cap_F: 0.00001; Tolerance_%: 10; VDC_V: 6.3; Value2: 6.3V; TaMin_C: -55; TaMax_C: 125; Cap_Case: 0805; SizeArea_mm2: 2.5; SizeAreaWB_mm2: 6.75; SizeX_mm: 2; SizeY_mm: 1.25; SizeZ_mm: 1.45; AEC Category: Q200; AEC Qualified: Y; AEC Grade: 1; Green_Lifecycle: Active; Green_REACh: Passed
signal-integrity model Cap
simulation model Cap
footprint 0805_HV
footprint 0805_HV1
footprint 0805
footprint 0805M
footprint 0805L
pins: 1, 2

## GCM21BR71A106KE22L
designator C?  ValueDisplayed: 10µF  (hidden comment: GCM21BR71A106KE22L)
CAP, CERM, 10 µF, 10 V,+/- 10%, X7R, AEC-Q200 Grade 1, 0805; Manufacturer: MuRata; Polarized: N; CompType: Capacitor; Value: 10uF; U/M: EA; Cap_F: 0.00001; Tolerance_%: 10; Value2: 10V; TaMin_C: -55; TaMax_C: 125; Cap_Case: 0805; SizeArea_mm2: 2.5; SizeAreaWB_mm2: 6.75; SizeX_mm: 2; SizeY_mm: 1.25; SizeZ_mm: 1.45; AEC Category: Q200; AEC Qualified: Y; AEC Grade: 1; Green_Lifecycle: Not Set; Green_REACh: Incomplete
signal-integrity model Cap
simulation model Cap
footprint 0805_HV
footprint 0805_HV1
footprint 0805
footprint 0805M
footprint 0805L
pins: 1, 2

## GCM21BR71C475KA73K
designator C?  ValueDisplayed: 4.7µF  (hidden comment: GCM21BR71C475KA73K)
CAP, CERM, 4.7 µF, 16 V,+/- 10%, X7R, AEC-Q200 Grade 1, 0805; Manufacturer: MuRata; Polarized: N; CompType: Capacitor; Value: 4.7uF; U/M: EA; Cap_F: 0.0000047; Tolerance_%: 10; VDC_V: 16; Value2: 16V; TaMin_C: -55; TaMax_C: 125; Cap_Case: 0805; SizeArea_mm2: 2.5; SizeAreaWB_mm2: 6.75; SizeX_mm: 2; SizeY_mm: 1.25; SizeZ_mm: 1.45; AEC Category: Q200; AEC Qualified: Y; AEC Grade: 1
signal-integrity model Cap
simulation model Cap
footprint 0805_HV
footprint 0805_HV1
footprint 0805
footprint 0805M
footprint 0805L
pins: 1, 2

## GCM21BR71C475KA73L
designator C?  ValueDisplayed: 4.7µF  (hidden comment: GCM21BR71C475KA73L)
CAP, CERM, 4.7 µF, 16 V,+/- 10%, X7R, AEC-Q200 Grade 1, 0805; Manufacturer: MuRata; Polarized: N; CompType: Capacitor; Value: 4.7uF; U/M: EA; Cap_F: 0.0000047; Tolerance_%: 10; VDC_V: 16; Value2: 16V; TaMin_C: -55; TaMax_C: 125; Cap_Case: 0805; SizeArea_mm2: 2.5; SizeAreaWB_mm2: 6.75; SizeX_mm: 2; SizeY_mm: 1.25; SizeZ_mm: 1.45; AEC Category: Q200; AEC Qualified: Y; AEC Grade: 1; Green_Lifecycle: Active; Green_REACh: Passed
signal-integrity model Cap
simulation model Cap
footprint 0805_HV
footprint 0805_HV1
footprint 0805
footprint 0805M
footprint 0805L
pins: 1, 2

## GCM21BR71H104KA37K
designator C?  ValueDisplayed: 0.1µF  (hidden comment: GCM21BR71H104KA37K)
CAP, CERM, 0.1 µF, 50 V,+/- 10%, X7R, AEC-Q200 Grade 1, 0805; Manufacturer: MuRata; Polarized: N; CompType: Capacitor; Value: 0.1uF; U/M: EA; Cap_F: 0.0000001; Tolerance_%: 10; VDC_V: 50; Value2: 50V; TaMin_C: -55; TaMax_C: 125; Cap_Case: 0805; SizeArea_mm2: 2.5; SizeAreaWB_mm2: 6.75; SizeX_mm: 2; SizeY_mm: 1.25; SizeZ_mm: 1.45; AEC Category: Q200; AEC Qualified: Y; AEC Grade: 1
signal-integrity model Cap
simulation model Cap
footprint 0805_HV
footprint 0805_HV1
footprint 0805
footprint 0805M
footprint 0805L
pins: 1, 2

## GCM21BR71H474KA55L
designator C?  ValueDisplayed: 0.47µF  (hidden comment: GCM21BR71H474KA55L)
CAP, CERM, 0.47 µF, 50 V,+/- 10%, X7R, AEC-Q200 Grade 1, 0805; Manufacturer: MuRata; Polarized: N; CompType: Capacitor; Value: 0.47uF; U/M: EA; Cap_F: 0.00000047; Tolerance_%: 10; VDC_V: 50; Value2: 50V; TaMin_C: -55; TaMax_C: 125; Cap_Case: 0805; SizeArea_mm2: 2.5; SizeAreaWB_mm2: 6.75; SizeX_mm: 2; SizeY_mm: 1.25; SizeZ_mm: 1.45; AEC Category: Q200; AEC Qualified: Y; AEC Grade: 1; Green_Lifecycle: Not Set; Green_REACh: Incomplete
signal-integrity model Cap
simulation model Cap
footprint 0805_HV
footprint 0805_HV1
footprint 0805
footprint 0805M
footprint 0805L
pins: 1, 2

## GCM21BR72A473KA37L
designator C?  ValueDisplayed: 0.047µF  (hidden comment: GCM21BR72A473KA37L)
CAP, CERM, 0.047 µF, 100 V,+/- 10%, X7R, AEC-Q200 Grade 1, 0805; Manufacturer: MuRata; Polarized: N; CompType: Capacitor; Value: 0.047uF; U/M: EA; Cap_F: 0.000000047; Tolerance_%: 10; VDC_V: 100; Value2: 100V; TaMin_C: -55; TaMax_C: 125; Cap_Case: 0805; SizeArea_mm2: 2.5; SizeAreaWB_mm2: 6.75; SizeX_mm: 2; SizeY_mm: 1.25; SizeZ_mm: 1.45; AEC Category: Q200; AEC Qualified: Y; AEC Grade: 1
signal-integrity model Cap
simulation model Cap
footprint 0805_HV
footprint 0805_HV1
footprint 0805
footprint 0805M
footprint 0805L
pins: 1, 2

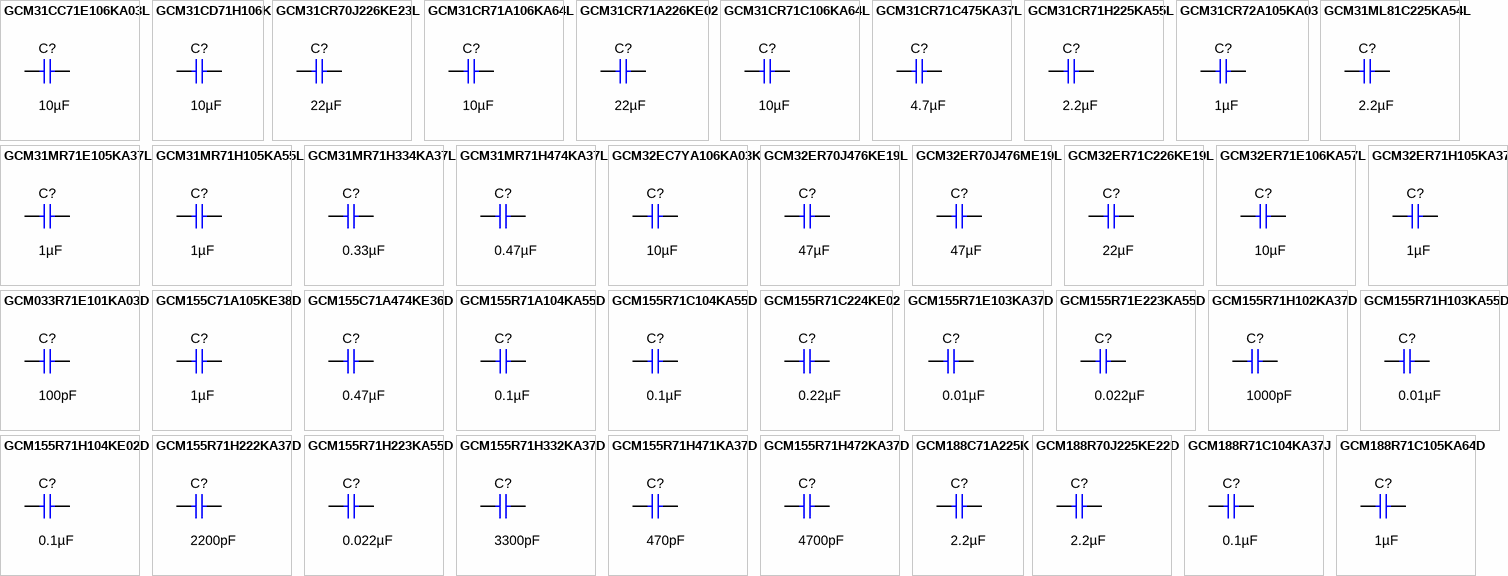
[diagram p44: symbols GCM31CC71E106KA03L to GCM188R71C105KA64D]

## GCM31CC71E106KA03L
designator C?  ValueDisplayed: 10µF  (hidden comment: GCM31CC71E106KA03L)
CAP, CERM, 10 µF, 25 V,+/- 10%, X7S, AEC-Q200 Grade 1, 1206; Manufacturer: MuRata; Polarized: N; CompType: Capacitor; Value: 10uF; U/M: EA; Cap_F: 0.00001; Tolerance_%: 10; VDC_V: 25; Value2: 25V; TaMin_C: -55; TaMax_C: 125; Cap_Case: 1206; SizeArea_mm2: 5.12; SizeAreaWB_mm2: 10.92; SizeX_mm: 3.2; SizeY_mm: 1.6; SizeZ_mm: 1.9; AEC Category: Q200; AEC Qualified: Y; AEC Grade: 1
signal-integrity model Cap
simulation model Cap
footprint 1206_190
footprint 1206_190M
footprint 1206_190L
pins: 1, 2

## GCM31CD71H106K
designator C?  ValueDisplayed: 10µF  (hidden comment: GCM31CD71H106K)
CAP, CERM, 10 µF, 50 V,+/- 10%, X7T, 1206; Manufacturer: MuRata; Polarized: N; CompType: Capacitor; Value: 10uF; U/M: EA; Cap_F: 0.00001; Tolerance_%: 10; VDC_V: 50; Value2: 50V; TaMin_C: -55; TaMax_C: 125; Cap_Case: 1206; SizeArea_mm2: 5.12; SizeAreaWB_mm2: 10.92; SizeX_mm: 3.2; SizeY_mm: 1.6; SizeZ_mm: 1.9; AEC Category: Q200
signal-integrity model Cap
simulation model Cap
footprint 1206_190
footprint 1206_190M
footprint 1206_190L
pins: 1, 2

## GCM31CR70J226KE23L
designator C?  ValueDisplayed: 22µF  (hidden comment: GCM31CR70J226KE23L)
CAP, CERM, 22 µF, 6.3 V,+/- 10%, X7R, AEC-Q200 Grade 1, 1206; Manufacturer: MuRata; Polarized: N; CompType: Capacitor; Value: 22uF; U/M: EA; Cap_F: 0.000022; Tolerance_%: 10; VDC_V: 6.3; Value2: 6.3V; TaMin_C: -55; TaMax_C: 125; Cap_Case: 1206; SizeArea_mm2: 5.12; SizeAreaWB_mm2: 10.92; SizeX_mm: 3.2; SizeY_mm: 1.6; SizeZ_mm: 1.8; AEC Category: Q200; AEC Qualified: Y; AEC Grade: 1
signal-integrity model Cap
simulation model Cap
footprint 1206_180
footprint 1206_180M
footprint 1206_180L
pins: 1, 2

## GCM31CR71A106KA64L
designator C?  ValueDisplayed: 10µF  (hidden comment: GCM31CR71A106KA64L)
CAP, CERM, 10 µF, 10 V,+/- 10%, X7R, AEC-Q200 Grade 1, 1206; Manufacturer: MuRata; Polarized: N; CompType: Capacitor; Value: 10uF; U/M: EA; Cap_F: 0.00001; Tolerance_%: 10; Value2: 10V; TaMin_C: -55; TaMax_C: 125; Cap_Case: 1206; SizeArea_mm2: 5.12; SizeAreaWB_mm2: 10.92; SizeX_mm: 3.2; SizeY_mm: 1.6; SizeZ_mm: 1.8; AEC Category: Q200; AEC Qualified: Y; AEC Grade: 1
signal-integrity model Cap
simulation model Cap
footprint 1206_180
footprint 1206_180M
footprint 1206_180L
pins: 1, 2

## GCM31CR71A226KE02
designator C?  ValueDisplayed: 22µF  (hidden comment: GCM31CR71A226KE02)
CAP, CERM, 22 µF, 10 V,+/- 10%, X7R, AEC-Q200 Grade 1, 1206; Manufacturer: MuRata; Polarized: N; CompType: Capacitor; Value: 22uF; U/M: EA; Cap_F: 0.000022; Tolerance_%: 10; Value2: 10V; TaMin_C: -55; TaMax_C: 125; Cap_Case: 1206; SizeArea_mm2: 5.12; SizeAreaWB_mm2: 10.92; SizeX_mm: 3.2; SizeY_mm: 1.6; SizeZ_mm: 1.8; AEC Category: Q200; AEC Qualified: Y; AEC Grade: 1
signal-integrity model Cap
simulation model Cap
footprint 1206_180
footprint 1206_180M
footprint 1206_180L
pins: 1, 2

## GCM31CR71C106KA64L
designator C?  ValueDisplayed: 10µF  (hidden comment: GCM31CR71C106KA64L)
CAP, CERM, 10 µF, 16 V,+/- 10%, X7R, AEC-Q200 Grade 1, 1206; Manufacturer: MuRata; Polarized: N; CompType: Capacitor; Value: 10uF; U/M: EA; Cap_F: 0.00001; Tolerance_%: 10; VDC_V: 16; Value2: 16V; TaMin_C: -55; TaMax_C: 125; Cap_Case: 1206; SizeArea_mm2: 5.12; SizeAreaWB_mm2: 10.92; SizeX_mm: 3.2; SizeY_mm: 1.6; SizeZ_mm: 1.8; AEC Category: Q200; AEC Qualified: Y; AEC Grade: 1; Green_Lifecycle: Active; Green_REACh: Passed
signal-integrity model Cap
simulation model Cap
footprint 1206_180
footprint 1206_180M
footprint 1206_180L
pins: 1, 2

## GCM31CR71C475KA37L
designator C?  ValueDisplayed: 4.7µF  (hidden comment: GCM31CR71C475KA37L)
CAP, CERM, 4.7 µF, 16 V,+/- 10%, X7R, AEC-Q200 Grade 1, 1206; Manufacturer: MuRata; Polarized: N; CompType: Capacitor; Value: 4.7uF; U/M: EA; Cap_F: 0.0000047; Tolerance_%: 10; VDC_V: 16; Value2: 16V; TaMin_C: -55; TaMax_C: 125; Cap_Case: 1206; SizeArea_mm2: 5.12; SizeAreaWB_mm2: 10.92; SizeX_mm: 3.2; SizeY_mm: 1.6; SizeZ_mm: 1.8; AEC Category: Q200; AEC Qualified: Y; AEC Grade: 1; Green_Lifecycle: Active; Green_REACh: Passed
signal-integrity model Cap
simulation model Cap
footprint 1206_180
footprint 1206_180M
footprint 1206_180L
pins: 1, 2

## GCM31CR71H225KA55L
designator C?  ValueDisplayed: 2.2µF  (hidden comment: GCM31CR71H225KA55L)
CAP, CERM, 2.2 µF, 50 V,+/- 10%, X7R, AEC-Q200 Grade 1, 1206; Manufacturer: MuRata; Polarized: N; CompType: Capacitor; Value: 2.2uF; U/M: EA; Cap_F: 0.0000022; Tolerance_%: 10; VDC_V: 50; Value2: 50V; TaMin_C: -55; TaMax_C: 125; Cap_Case: 1206; SizeArea_mm2: 5.12; SizeAreaWB_mm2: 10.92; SizeX_mm: 3.2; SizeY_mm: 1.6; SizeZ_mm: 1.8; AEC Category: Q200; AEC Qualified: Y; AEC Grade: 1; Green_Lifecycle: Active; Green_REACh: Passed
signal-integrity model Cap
simulation model Cap
footprint 1206_180
footprint 1206_180M
footprint 1206_180L
pins: 1, 2

## GCM31CR72A105KA03
designator C?  ValueDisplayed: 1µF  (hidden comment: GCM31CR72A105KA03)
CAP, CERM, 1 µF, 100 V,+/- 10%, X7R, AEC-Q200 Grade 1, 1206; Manufacturer: MuRata; Polarized: N; CompType: Capacitor; Value: 1uF; U/M: EA; Cap_F: 0.000001; Tolerance_%: 10; VDC_V: 100; Value2: 100V; TaMin_C: -55; TaMax_C: 125; Cap_Case: 1206; SizeArea_mm2: 5.12; SizeAreaWB_mm2: 10.92; SizeX_mm: 3.2; SizeY_mm: 1.6; SizeZ_mm: 1.8; AEC Category: Q200; AEC Qualified: Y; AEC Grade: 1
signal-integrity model Cap
simulation model Cap
footprint 1206_180
footprint 1206_180M
footprint 1206_180L
pins: 1, 2

## GCM31ML81C225KA54L
designator C?  ValueDisplayed: 2.2µF  (hidden comment: GCM31ML81C225KA54L)
CAP, CERM, 2.2 µF, 16 V,+/- 10%, X8L, AEC-Q200 Grade 0, 1206; Manufacturer: MuRata; Polarized: N; CompType: Capacitor; Value: 2.2uF; U/M: EA; Cap_F: 0.0000022; Tolerance_%: 10; VDC_V: 16; Value2: 16V; TaMin_C: -55; TaMax_C: 150; Cap_Case: 1206; SizeArea_mm2: 5.12; SizeAreaWB_mm2: 10.92; SizeX_mm: 3.2; SizeY_mm: 1.6; SizeZ_mm: 1.4; AEC Category: Q200; AEC Qualified: Y; AEC Grade: 0
signal-integrity model Cap
simulation model Cap
footprint 1206_140
footprint 1206_140M
footprint 1206_140L
pins: 1, 2

## GCM31MR71E105KA37L
designator C?  ValueDisplayed: 1µF  (hidden comment: GCM31MR71E105KA37L)
CAP, CERM, 1 µF, 25 V,+/- 10%, X7R, AEC-Q200 Grade 1, 1206; Manufacturer: MuRata; Polarized: N; CompType: Capacitor; Value: 1uF; U/M: EA; Cap_F: 0.000001; Tolerance_%: 10; VDC_V: 25; Value2: 25V; TaMin_C: -55; TaMax_C: 125; Cap_Case: 1206; SizeArea_mm2: 5.12; SizeAreaWB_mm2: 10.92; SizeX_mm: 3.2; SizeY_mm: 1.6; SizeZ_mm: 1.35; AEC Category: Q200; AEC Qualified: Y; AEC Grade: 1; Green_Lifecycle: Active; Green_REACh: Passed
signal-integrity model Cap
simulation model Cap
footprint 1206
footprint 1206M
footprint 1206L
pins: 1, 2

## GCM31MR71H105KA55L
designator C?  ValueDisplayed: 1µF  (hidden comment: GCM31MR71H105KA55L)
CAP, CERM, 1 µF, 50 V,+/- 10%, X7R, AEC-Q200 Grade 1, 1206; Manufacturer: MuRata; Polarized: N; CompType: Capacitor; Value: 1uF; U/M: EA; Cap_F: 0.000001; Tolerance_%: 10; VDC_V: 50; Value2: 50V; TaMin_C: -55; TaMax_C: 125; Cap_Case: 1206; SizeArea_mm2: 5.12; SizeAreaWB_mm2: 10.92; SizeX_mm: 3.2; SizeY_mm: 1.6; SizeZ_mm: 1.35; AEC Category: Q200; AEC Qualified: Y; AEC Grade: 1
signal-integrity model Cap
simulation model Cap
footprint 1206
footprint 1206M
footprint 1206L
pins: 1, 2

## GCM31MR71H334KA37L
designator C?  ValueDisplayed: 0.33µF  (hidden comment: GCM31MR71H334KA37L)
CAP, CERM, 0.33 µF, 50 V,+/- 10%, X7R, AEC-Q200 Grade 1, 1206; Manufacturer: MuRata; Polarized: N; CompType: Capacitor; Value: 0.33uF; U/M: EA; Cap_F: 0.00000033; Tolerance_%: 10; VDC_V: 50; Value2: 50V; TaMin_C: -55; TaMax_C: 125; Cap_Case: 1206; SizeArea_mm2: 5.12; SizeAreaWB_mm2: 10.92; SizeX_mm: 3.2; SizeY_mm: 1.6; SizeZ_mm: 1.35; AEC Category: Q200; AEC Qualified: Y; AEC Grade: 1
signal-integrity model Cap
simulation model Cap
footprint 1206
footprint 1206M
footprint 1206L
pins: 1, 2

## GCM31MR71H474KA37L
designator C?  ValueDisplayed: 0.47µF  (hidden comment: GCM31MR71H474KA37L)
CAP, CERM, 0.47 µF, 50 V,+/- 10%, X7R, AEC-Q200 Grade 1, 1206; Manufacturer: MuRata; Polarized: N; CompType: Capacitor; Value: 0.47uF; U/M: EA; Cap_F: 0.00000047; Tolerance_%: 10; VDC_V: 50; Value2: 50V; TaMin_C: -55; TaMax_C: 125; Cap_Case: 1206; SizeArea_mm2: 5.12; SizeAreaWB_mm2: 10.92; SizeX_mm: 3.2; SizeY_mm: 1.6; SizeZ_mm: 1.35; AEC Category: Q200; AEC Qualified: Y; AEC Grade: 1
signal-integrity model Cap
simulation model Cap
footprint 1206
footprint 1206M
footprint 1206L
pins: 1, 2

## GCM32EC7YA106KA03K
designator C?  ValueDisplayed: 10µF  (hidden comment: GCM32EC7YA106KA03K)
CAP, CERM, 10 µF, 35 V,+/- 10%, X7S, AEC-Q200 Grade 1, 1210; Manufacturer: MuRata; Polarized: N; CompType: Capacitor; Value: 10uF; U/M: EA; Cap_F: 0.00001; Tolerance_%: 10; VDC_V: 35; Value2: 35V; TaMin_C: -55; TaMax_C: 125; Cap_Case: 1210; SizeArea_mm2: 8; SizeAreaWB_mm2: 14.7; SizeX_mm: 3.2; SizeY_mm: 2.5; SizeZ_mm: 2.8; AEC Category: Q200; AEC Qualified: Y; AEC Grade: 1
signal-integrity model Cap
simulation model Cap
footprint 1210_280
pins: 1, 2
